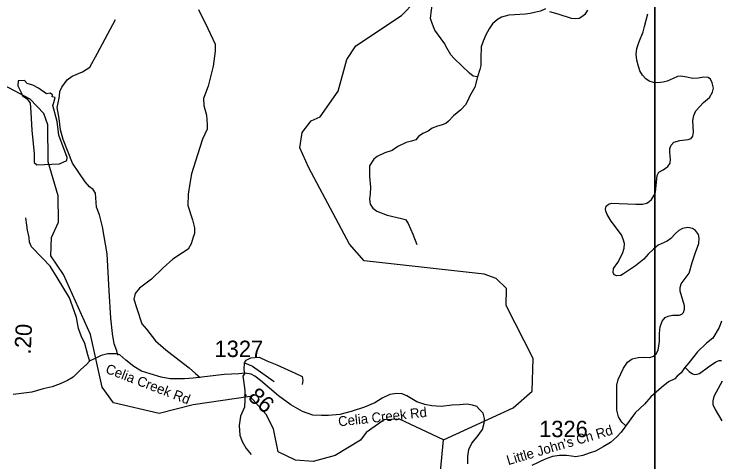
# Model space of a CAD drawing. Extents: x 1159738 to 1321356, y 736314 to 882035.
# Drawn here: x 1208685 to 1214073, y 786195 to 789615 of the extents above; entities that cross this region are included whole.
import ezdxf

# ---------------------------------------------------------------- set-up
doc = ezdxf.new("R2010")
doc.units = 0
for name, color, linetype in [('Exist Hydrographic Creek Single Shore', 7, 'Continuous'), ('Exist Hydrographic Misc Water Feature', 7, 'Continuous'), ('Exist Hydrographic Pond Under 1500 Sq Ft', 7, 'Continuous'), ('Exist Road Non-System Type 51', 7, 'Continuous'), ('Exist Road Secondary Mileage Hundredths English Label', 7, 'Continuous'), ('Exist Road Secondary Type 51 Attributed', 7, 'Continuous'), ('Exist Road Secondary Type 51 Label', 7, 'Continuous'), ('Exist Road Secondary Type 51 Number Label', 7, 'Continuous'), ('Map Preparation Inset Cut Line', 7, 'Continuous')]:
    doc.layers.add(name, color=color, linetype=linetype)

msp = doc.modelspace()

# ---------------------------------------------------------------- linework, layer by layer
at = {"layer": 'Exist Hydrographic Creek Single Shore'}
for points in [[(1211962.7, 786362), (1212494.7, 786607.4), (1212640.7, 786735.8), (1212646.8, 786985.2), (1212441.7, 787389.7), (1212444.7, 787517.6), (1212363.7, 787594.8), (1212272.7, 787629.5), (1211357.7, 787729.8), (1211244.7, 787856.9), (1210935.7, 788440.7), (1210864.6, 788593.2), (1210884.6, 788710.9), (1210953.6, 788798.2), (1211020.7, 788829.7), (1211159.6, 789027.1), (1211224.6, 789268.8), (1211293.6, 789372.4), (1211642.6, 789605), (1211745.6, 789711.3), (1211754.7, 789770.1)], [(1212191.3, 784800.4), (1212136.8, 785088.2), (1212098.7, 785200.6), (1211916.8, 785880.4), (1211962.7, 786362)]]:
    msp.add_lwpolyline(points, dxfattribs=at)
at = {"layer": 'Exist Hydrographic Misc Water Feature'}
msp.add_lwpolyline([(1211962.7, 786362), (1211625.7, 786519.8), (1211508.7, 786515.6), (1211372.7, 786419.8), (1211329.7, 786361.6), (1211134.7, 786244.1), (1210966.7, 786198.2), (1210832.7, 786207.4), (1210701.7, 786272.4), (1210664.7, 786447.1), (1210608.7, 786556.6), (1210487.7, 786693.5), (1210052.7, 786630.1), (1209791.7, 786563.1), (1209443.6, 786645.6), (1209355.7, 786765.5), (1209266.7, 787167.7), (1209061.6, 787624.8), (1208965.7, 787768), (1208969.7, 787909), (1209022.7, 788026.1), (1209019.7, 788226.4), (1208943.6, 788487.2), (1208942.6, 788769.5), (1208911.6, 788855.6), (1208806.6, 788966), (1208403.6, 789177.5)], dxfattribs=at)
at = {"layer": 'Exist Hydrographic Pond Under 1500 Sq Ft'}
msp.add_lwpolyline([(1208715.7, 789104.6), (1208711.9, 789066.8), (1208738.4, 789015.7), (1208749.7, 788991.2), (1208783.7, 788968.5), (1208806.4, 788934.4), (1208812.1, 788864.5), (1208819.6, 788724.6), (1208838.5, 788550.6), (1208836.6, 788480.7), (1208857.4, 788463.7), (1209031.2, 788471.2), (1209087.9, 788497.7), (1209089.8, 788520.4), (1209025.6, 788688.7), (1209012.3, 788794.5), (1208980.2, 788915.5), (1208987.8, 788938.2), (1208999.1, 788977.9), (1208974.5, 788983.6), (1208976.4, 788998.7), (1208959.4, 789010.1), (1208931.1, 789006.3), (1208870.6, 789049.8), (1208827.2, 789072.5), (1208783.7, 789083.8), (1208762.9, 789106.5)], close=True, dxfattribs=at)
at = {"layer": 'Exist Road Non-System Type 51'}
for points in [[(1212223, 789135.1), (1212189.5, 789141.8), (1212160.1, 789164.5), (1212043.7, 789275.6), (1212019.6, 789303.8), (1211979.5, 789369.3), (1211972.8, 789386.7), (1211896.6, 789492.5), (1211872.5, 789550.1), (1211864.4, 789582.2), (1211869.8, 789646.4), (1211877.8, 789689.3), (1211901.9, 789762.9), (1211938, 789831.8), (1212033, 789961.6), (1212110.6, 790059.3), (1212152.1, 790118.2), (1212157.4, 790139.6), (1212152.1, 790159.7), (1212141.4, 790173.1), (1212066.4, 790205.2), (1211998.3, 790225.9)], [(1210091.9, 789650.4), (1210164.2, 789505.7), (1210219.8, 789384.1), (1210219.8, 789331.3), (1210203.1, 789217.2), (1210166.9, 789064.2), (1210130.8, 788970.5), (1210133.6, 788917.7), (1210153.1, 788842.6), (1210158.6, 788770.2), (1210158.6, 788736.9), (1210122.5, 788659), (1210083.7, 788540.2), (1210039.2, 788395.5), (1210025.3, 788320.4), (1210014.2, 788239.8), (1210011.4, 788153.5), (1210047.6, 788043.6), (1210061.5, 787982.4), (1210061.5, 787937.9), (1210050.3, 787910.1), (1210036.4, 787860.1), (1210014.2, 787818.3), (1209969.7, 787790.5), (1209897.5, 787743.2), (1209822.4, 787676.5), (1209733.5, 787590.2), (1209641.7, 787520.7), (1209608.4, 787481.8), (1209597.3, 787437.3), (1209622.3, 787364.9), (1209658.6, 787248.9), (1209694.7, 787207.2), (1209764.2, 787118.2), (1209842, 787051.4), (1209944.9, 786970.8), (1210019.9, 786912.3), (1210070, 786870.6), (1210106.1, 786837.9)], [(1212740.3, 789655.4), (1212702.7, 789636.3), (1212658.6, 789626.9), (1212623.8, 789618.9), (1212589, 789613.5), (1212461.9, 789605.5), (1212404.9, 789591.2), (1212374.1, 789573.8), (1212338, 789540.4), (1212311.2, 789501.5), (1212285.8, 789456), (1212264.4, 789407.8), (1212251.1, 789365), (1212247, 789279.3), (1212248.4, 789220.8), (1212240.3, 789191.3), (1212223, 789135.1)], [(1213062.8, 789643.4), (1213042.8, 789611.4), (1213025.5, 789599.4), (1212998.8, 789580.8), (1212973.5, 789578.1), (1212938.9, 789580.8), (1212838.9, 789614.1), (1212774.9, 789631.4)], [(1209475.3, 787010), (1209469.6, 787042.1), (1209448.8, 787097), (1209435.6, 787174.5), (1209422.4, 787291.7), (1209411, 787501.6), (1209394, 787782.6), (1209358.1, 787990.6), (1209335.4, 788081.3), (1209314.6, 788139.9), (1209305.2, 788245.8), (1209288.3, 788275.3), (1209259.9, 788294.2), (1209227.8, 788333.9), (1209131.5, 788475.7), (1209059.7, 788656.4), (1209038.9, 788730.1), (1209027.6, 788817.1), (1209012.5, 788900.3), (1209029.4, 788973.3), (1209031.3, 788990.3), (1209033.2, 789024.3), (1209048.3, 789056.5), (1209089.9, 789113.2), (1209127.7, 789141.5), (1209207, 789173.7), (1209263.7, 789209.6), (1209320.4, 789315.5), (1209459.7, 789573.7)], [(1213982.7, 789131.2), (1213950.7, 789133.8), (1213908.1, 789124.5), (1213862.8, 789121.8), (1213821.5, 789132.5), (1213773.5, 789140.5), (1213749.5, 789139.2), (1213714.9, 789123.2), (1213669.5, 789101.8), (1213640.2, 789095.2), (1213598.9, 789089.8), (1213566.9, 789092.5), (1213533.6, 789101.8), (1213508.3, 789119.2), (1213483, 789147.2), (1213461.6, 789180.5), (1213448.3, 789224.5), (1213437.7, 789261.9), (1213434.2, 789309), (1213438.2, 789351.7), (1213452.9, 789397), (1213486.2, 789479.7), (1213498.2, 789519.7), (1213523.5, 789617.1)], [(1212223, 789135.1), (1212200.8, 789057.8), (1212161.7, 788984.3), (1212151, 788959.4), (1212129.7, 788922.6), (1212094.1, 788884.7), (1212038.4, 788837.2), (1212001.7, 788798.1), (1211980.4, 788780.3), (1211946, 788766.1), (1211917.5, 788758.9), (1211874.9, 788742.3), (1211845.2, 788719.8), (1211806.1, 788702), (1211771.7, 788680.6), (1211751.6, 788653.4), (1211717.7, 788644.4), (1211678.6, 788634.9), (1211614.6, 788602.9), (1211569.5, 788572), (1211515, 788554.3), (1211456.9, 788527), (1211430.9, 788505.6), (1211398.9, 788457), (1211397.7, 788417.8), (1211396.5, 788375.1), (1211406.2, 788291.6), (1211403.8, 788241.8), (1211396.7, 788201.5), (1211402.6, 788163.5), (1211422.8, 788132.7), (1211454.8, 788110.2), (1211533, 788079.3), (1211643.2, 788053.2), (1211672.9, 788044.9), (1211693, 788015.3), (1211727.4, 787933.4), (1211759.2, 787854.5)], [(1213354.3, 786469), (1213323.7, 786498.3), (1213298.4, 786539.7), (1213285, 786590.3), (1213286.4, 786781), (1213297, 786823.7), (1213335.7, 786909.1), (1213366.3, 786955.8), (1213403.7, 786982.4), (1213447.6, 786993.1), (1213492.9, 786994.4), (1213536.9, 786993.1), (1213564.9, 787001.1), (1213586.2, 787019.8), (1213600.9, 787049.1), (1213612.7, 787114.6), (1213612.7, 787174.6), (1213616.7, 787225.3), (1213632.7, 787269.3), (1213655.3, 787298.6), (1213678, 787308), (1213711.3, 787314.6), (1213760.6, 787316), (1213781.9, 787324), (1213793.9, 787336), (1213803.3, 787361.3), (1213801.9, 787386.7), (1213768.6, 787497.3), (1213768.6, 787526.7), (1213777.9, 787553.4), (1213837.9, 787634.7), (1213860.4, 787716.7), (1213887.1, 787794.1), (1213912.4, 787862.1), (1213915.1, 787903.4), (1213909.7, 787930.1), (1213885.7, 787960.8), (1213863.1, 787976.8), (1213828.4, 787984.8), (1213788.5, 787976.8), (1213759.1, 787962.1), (1213733.8, 787938.1), (1213699.2, 787900.7), (1213671.2, 787880.7), (1213600.5, 787848.7), (1213565.9, 787819.4), (1213525.9, 787780.7), (1213491.3, 787743.4), (1213428.6, 787692.7), (1213338, 787631.3), (1213315.3, 787618), (1213286, 787615.3), (1213264.7, 787623.3), (1213258, 787640.7), (1213260.7, 787671.4), (1213292.7, 787718), (1213330, 787786.1), (1213340.7, 787827.4), (1213343.3, 787862.1), (1213334, 787896.7), (1213322, 787928.7), (1213243.4, 788034.1), (1213211.7, 788083), (1213201.1, 788108.3), (1213198.4, 788125.6), (1213205.1, 788147), (1213221.1, 788163), (1213247.7, 788169.6), (1213303.7, 788168.3), (1213431.6, 788163), (1213482.3, 788163), (1213514.3, 788169.6), (1213532.9, 788183), (1213551.6, 788199), (1213568.9, 788225.7), (1213582.2, 788256.3), (1213592.9, 788383), (1213606.2, 788407), (1213639.5, 788424.4), (1213675.1, 788451.8), (1213692.4, 788475.8), (1213695.1, 788506.4), (1213689.8, 788558.4), (1213689.8, 788587.8), (1213700.4, 788613.1), (1213721.7, 788635.8), (1213765.7, 788649.1), (1213829.7, 788657.1), (1213853.7, 788663.8), (1213867, 788682.5), (1213872.3, 788713.1), (1213867, 788801.2), (1213874.8, 788839.1), (1213888.1, 788875.1), (1213946.7, 788940.5), (1213993.4, 788977.8), (1214016, 789017.8), (1214022.7, 789048.5), (1214014.7, 789088.5), (1214000.1, 789116.5), (1213982.7, 789131.2)], [(1209263.5, 786960.6), (1209248.3, 787011.7), (1209225.7, 787098.7), (1209197.3, 787157.3), (1209176.6, 787214), (1209161.4, 787297.2), (1209129.3, 787384.1), (1209108.5, 787448.4), (1209014.1, 787601.6), (1208959.3, 787690.4), (1208898.8, 787752.8), (1208817.6, 787836), (1208802.5, 787873.8), (1208798.7, 787907.9), (1208785.7, 787963.8), (1208781.9, 788003.5), (1208774.3, 788058.3)], [(1210442.7, 786952.3), (1210456.3, 786972), (1210491.9, 786988.1), (1210554.4, 786995.3), (1210613.3, 786966.7), (1210690, 786936.3), (1210830.9, 786872.1), (1210884.4, 786847.1), (1210888, 786814.9), (1210882.7, 786784.6)], [(1210445.3, 786871), (1210440.9, 786898.8), (1210442.7, 786952.3)], [(1210442.7, 786952.3), (1210504.5, 786925.5), (1210668.7, 786807.7)], [(1213811.2, 786912.1), (1213839.1, 786885.3), (1213862.5, 786867.5), (1213880.4, 786861.9), (1213900.5, 786865.2), (1213918.3, 786870.8), (1213986.4, 786921.1), (1214041.1, 786957.9), (1214067.9, 786968), (1214085.7, 786968)], [(1210445.3, 786871), (1210431.8, 786849.6), (1210435.3, 786815.6), (1210446, 786740.7), (1210446, 786665.7), (1210442.5, 786612.1), (1210413.9, 786542.5), (1210403.2, 786472.9)], [(1214091.3, 786810.5), (1214044.4, 786726.7), (1214025.5, 786694.4), (1214019.9, 786662), (1214019.9, 786634), (1214036.6, 786593.8), (1214088, 786509)], [(1210403.2, 786472.9), (1210408.8, 786399.9), (1210426.6, 786349.9), (1210455.2, 786296.4), (1210494.4, 786250)]]:
    msp.add_lwpolyline(points, dxfattribs=at)
at = {"layer": 'Exist Road Secondary Type 51 Attributed'}
for points in [[(1214083.9, 787268.8), (1214067.8, 787220.6), (1214020.1, 787139.2), (1213970.1, 787101.7), (1213900.6, 787035.7), (1213836.3, 786951.7), (1213803.4, 786912), (1213776.2, 786873.8), (1213747.6, 786848.8), (1213729.8, 786829.1), (1213681.6, 786805.9), (1213626.3, 786763.1), (1213546, 786691.7), (1213497.9, 786634.5), (1213426.5, 786568.5), (1213347.8, 786460.1), (1213318, 786421.2), (1213284.1, 786383.7), (1213237.8, 786342.6), (1213182.4, 786310.5), (1213123.6, 786276.5), (1213075.4, 786260.5), (1213027.2, 786242.6), (1212973.7, 786233.7), (1212939.8, 786237.3), (1212902.3, 786244.4), (1212847, 786242.6), (1212795.3, 786235.5), (1212738.2, 786215.8), (1212636.5, 786167.6)], [(1212149.5, 786179), (1212147.7, 786236.1), (1212156.7, 786289.7), (1212179.9, 786337.9), (1212219.1, 786386.1), (1212260.1, 786441.4), (1212272.6, 786489.6), (1212274.4, 786527.1), (1212265.5, 786566.4), (1212237, 786595), (1212217.3, 786616.4), (1212185.2, 786627.1), (1212140.6, 786636), (1212085.3, 786630.7), (1212030, 786627.1), (1211946.1, 786616.4), (1211873, 786621.7), (1211819.5, 786632.5), (1211758.8, 786652.1), (1211683.9, 786698.5), (1211646.4, 786714.6), (1211607.2, 786718.1), (1211551.9, 786709.2), (1211494.8, 786680.7), (1211437.7, 786646.7), (1211359.2, 786612.8), (1211257.1, 786578.2), (1211171.5, 786556.8), (1211084, 786549.6), (1211030.5, 786547.8), (1210966.3, 786551.4), (1210886, 786578.2), (1210796.8, 786630), (1210704, 786697.8), (1210566.6, 786817.4), (1210522, 786849.6), (1210493.5, 786863.8), (1210445.3, 786871), (1210400.7, 786867.4), (1210288.3, 786862.1), (1210161.7, 786846), (1210052.2, 786834.8), (1209984.5, 786829.5), (1209930.9, 786827.7), (1209875.6, 786829.5), (1209806, 786842), (1209724, 786867), (1209656.2, 786888.4), (1209599.1, 786924.1), (1209536.6, 786972.3), (1209492, 787011.6), (1209463.5, 787018.7), (1209432.8, 787020.9), (1209400.6, 787020.9), (1209348.9, 787006.6), (1209302.5, 786985.2), (1209263.3, 786965.5), (1209236.5, 786938.7), (1209193.7, 786901.2), (1209166.9, 786870.9), (1209134.8, 786842.3), (1209092, 786815.5), (1209034.9, 786790.6), (1208976, 786767.3), (1208906.4, 786753.1), (1208819, 786728.1), (1208678.1, 786710.2)]]:
    msp.add_lwpolyline(points, dxfattribs=at)
at = {"layer": 'Map Preparation Inset Cut Line'}
for points in [[(1213574.8, 811005.5), (1289258, 811005.5), (1289258, 782300.2), (1274049.2, 782296.9), (1274049.2, 766757), (1213574.8, 766757)], [(1213574.8, 778108.9), (1194107.7, 778108.9), (1194107.7, 805981), (1213574.8, 805981)]]:
    msp.add_lwpolyline(points, close=True, dxfattribs=at)

# ---------------------------------------------------------------- texts
at = {"layer": 'Exist Road Secondary Mileage Hundredths English Label'}
for s, rotation, p in [('.20', 87.1955, (1208811.1, 787013.7)), ('.86', 318.9532, (1210426.8, 786710))]:
    msp.add_text(s, height=125, rotation=rotation, dxfattribs=at).set_placement(p)
at = {"layer": 'Exist Road Secondary Type 51 Label'}
for s, rotation, p in [('Celia Creek Rd', 338.9273, (1209376.6, 786876.4)), ('Celia Creek Rd', 6.1985, (1211162.7, 786465.2)), ("Little John's Ch Rd", 16.3736, (1212456.9, 786169.1))]:
    msp.add_text(s, height=75, rotation=rotation, dxfattribs=at).set_placement(p)
at = {"layer": 'Exist Road Secondary Type 51 Number Label'}
for s, p in [('1327', (1210214.3, 786995.5)), ('1326', (1212692.5, 786383.4))]:
    msp.add_text(s, height=125, dxfattribs=at).set_placement(p)

doc.saveas('drawing.dxf')
